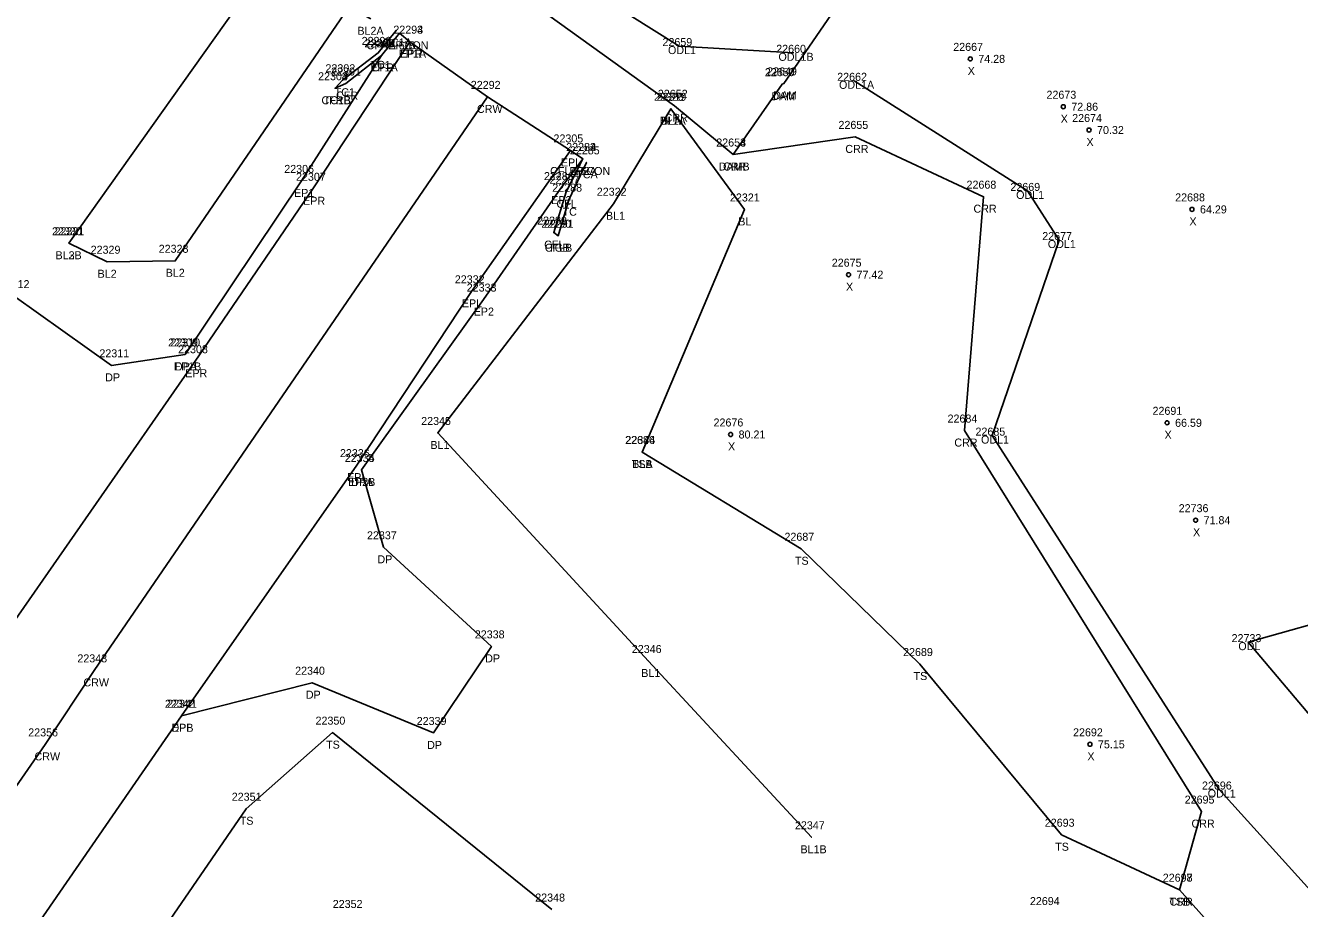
# Model space of a CAD drawing. Extents: x 2266664 to 2272385, y 716533 to 724777.
# Drawn here: x 2271014.2 to 2271173.4, y 722788.6 to 722898.9 of the extents above; entities that cross this region are included whole.
import ezdxf

# ---------------------------------------------------------------- set-up
doc = ezdxf.new("R2010")
doc.units = 0
for name, color, linetype in [('RD_DTM_BkLn1', 7, 'Continuous'), ('RD_DTM_BkLn2', 7, 'Continuous'), ('RD_EX_Conc', 7, 'Continuous'), ('RD_EX_Conc_txCode', 7, 'Continuous'), ('RD_EX_Dam', 7, 'Continuous'), ('RD_EX_Dam_txCode', 7, 'Continuous'), ('RD_EX_Driveway', 7, 'Continuous'), ('RD_EX_Driveway_txCode', 7, 'Continuous'), ('RD_EX_H2O', 7, 'Continuous'), ('RD_EX_H2O_txCode', 7, 'Continuous'), ('RD_EX_Road', 7, 'Continuous'), ('RD_EX_Road_txCode', 7, 'Continuous'), ('RD_Sketch8', 7, 'Continuous'), ('RD_SMD_Locator', 7, 'Continuous'), ('RD_SMD_Misc', 7, 'Continuous')]:
    doc.layers.add(name, color=color, linetype=linetype)

msp = doc.modelspace()

# ---------------------------------------------------------------- linework, layer by layer
at = {"layer": 'RD_DTM_BkLn1'}
for points in [[(2271062.16, 722908.42), (2271054.75, 722912.5), (2271044.28, 722906.51), (2271019.61, 722871.71)], [(2271057.34, 722899.76), (2271054.56, 722901.22), (2271032.9, 722869.52), (2271024.4, 722869.4), (2271019.61, 722871.71)], [(2271071.9, 722890), (2271022.74, 722818.33), (2271016.63, 722809.08), (2270958.33, 722725.01), (2270901.32, 722642.18), (2270840.59, 722553.52), (2270785.24, 722472.83), (2270728.9, 722390.97), (2270676.09, 722314.01), (2270618.86, 722231.46), (2270562.47, 722149.97), (2270509.04, 722072.31)], [(2271094.83, 722888.51), (2271087.64, 722876.65), (2271065.7, 722848), (2271092.04, 722819.5), (2271112.4, 722797.47)], [(2271094.83, 722888.51), (2271104, 722875.93), (2271091.22, 722845.62)]]:
    msp.add_lwpolyline(points, dxfattribs=at)
at = {"layer": 'RD_DTM_BkLn2'}
for points in [[(2271060.48, 722898.3), (2271058.25, 722895.5), (2271053.77, 722892.08), (2271052.86, 722891.08)], [(2271084.28, 722881.82), (2271082.08, 722877.15), (2271080.75, 722872.65)], [(2271091.22, 722845.62), (2271111.11, 722833.53), (2271125.94, 722819.12), (2271143.64, 722797.79), (2271158.38, 722790.92)], [(2271079.95, 722788.44), (2271052.54, 722810.55), (2271041.74, 722801.04), (2270977.44, 722707.42), (2270923.09, 722625.66), (2270862.03, 722536.61), (2270804.48, 722457.1), (2270748.57, 722375.78), (2270696.23, 722299.13), (2270638.45, 722212.76), (2270584.52, 722135.08), (2270530.44, 722055.94)]]:
    msp.add_lwpolyline(points, dxfattribs=at)
at = {"layer": 'RD_EX_Conc'}
for points in [[(2271060.91, 722897.95), (2271058.68, 722895.19), (2271054.21, 722891.67), (2271052.86, 722891.08)], [(2271083.82, 722882.24), (2271081.73, 722878.14), (2271080.19, 722873.04), (2271080.75, 722872.65)]]:
    msp.add_lwpolyline(points, dxfattribs=at)
at = {"layer": 'RD_EX_Dam'}
msp.add_lwpolyline([(2271152.21, 722956.41), (2271134.6, 722929.34), (2271126.04, 722916.39), (2271125.72, 722916.12), (2271108.94, 722891.69), (2271108.71, 722891.59), (2271102.6, 722882.8)], dxfattribs=at)
at = {"layer": 'RD_EX_Driveway'}
for points in [[(2271034.11, 722857.81), (2271024.92, 722856.45), (2271012.76, 722865.1), (2271006.76, 722871.86), (2270994.96, 722862.93), (2271003.93, 722846.02), (2271009.12, 722830.75), (2271009.25, 722819.48)], [(2271056.15, 722843.38), (2271058.93, 722833.71), (2271072.4, 722821.33), (2271065.14, 722810.51), (2271049.99, 722816.79), (2271033.67, 722812.66)]]:
    msp.add_lwpolyline(points, dxfattribs=at)
at = {"layer": 'RD_EX_H2O'}
for points in [[(2271066.1, 722930.8), (2271065.74, 722921.6), (2271073.98, 722910.09), (2271095.87, 722896.35), (2271110.14, 722895.51)], [(2271064.14, 722911.29), (2271095.29, 722888.89), (2271102.6, 722882.8), (2271117.86, 722885), (2271133.88, 722877.53), (2271131.49, 722848.3), (2271161.12, 722800.68), (2271158.38, 722790.92), (2271209.97, 722733.05), (2271257.97, 722699.07), (2271328.71, 722663.53), (2271328.76, 722676.23), (2271359.03, 722679.94), (2271405.02, 722657.62), (2271442.98, 722642.77), (2271440.33, 722616.88), (2271427.19, 722613.92), (2271489.22, 722575.87)], [(2271129.36, 722911.84), (2271153.18, 722901.48), (2271155.78, 722900.51), (2271177.85, 722902.74), (2271201.84, 722887.34), (2271215.1, 722884.79), (2271219.95, 722858.82), (2271232.72, 722821.83), (2271249.45, 722774.17), (2271246.55, 722773.42), (2271242.67, 722777.55), (2271238.21, 722784.89), (2271226, 722791.87), (2271212.02, 722807.07), (2271179.99, 722825.53), (2271166.96, 722821.86), (2271183.23, 722802.58), (2271216.87, 722768.55), (2271264.5, 722731.34), (2271320.51, 722707.37), (2271341.1, 722714.58), (2271416.82, 722677.3), (2271508.46, 722629.61)], [(2271117.72, 722892.01), (2271139.37, 722878.25), (2271143.33, 722872.11), (2271134.98, 722847.67), (2271163.31, 722803.44), (2271218.79, 722742.09), (2271259.36, 722713.19), (2271326.22, 722679.37), (2271360.14, 722683.15), (2271408.13, 722662.76), (2271445.34, 722648.77), (2271452.06, 722619.67), (2271495.73, 722594.36)]]:
    msp.add_lwpolyline(points, dxfattribs=at)
at = {"layer": 'RD_EX_Road'}
for p, q in [((2271062.22, 722896.9), (2271060.91, 722897.95)), ((2271082.27, 722883.31), (2271083.82, 722882.24))]:
    msp.add_line(p, q, dxfattribs=at)
for points in [[(2271062.22, 722896.9), (2271050.1, 722878.52), (2271035.36, 722856.97), (2271009.25, 722819.48), (2270948.68, 722732.14), (2270891.73, 722649.3), (2270830.29, 722559.72), (2270774.71, 722479.03), (2270718.54, 722397.26), (2270665.83, 722320.36), (2270608.79, 722237.92), (2270552.34, 722156.58), (2270498.7, 722078.55)], [(2271082.27, 722883.31), (2271071.9, 722890), (2271062.22, 722896.9)], [(2271058.68, 722895.19), (2271048.65, 722879.5), (2271034.11, 722857.81)], [(2271082.27, 722883.31), (2271069.9, 722865.7), (2271055.57, 722843.98), (2271033.67, 722812.66), (2270967.43, 722716.72), (2270911.49, 722634.76), (2270850.44, 722546.34), (2270794.45, 722465.06), (2270738.33, 722383.22), (2270685.67, 722306.46), (2270626.75, 722221.55), (2270572.84, 722143.55), (2270518.64, 722064.54)], [(2271083.82, 722882.24), (2271081.07, 722878.6), (2271071.39, 722864.67), (2271056.15, 722843.38)]]:
    msp.add_lwpolyline(points, dxfattribs=at)
at = {"layer": 'RD_SMD_Locator'}
for centre, radius in [((2271060.48, 722898.3), 0.001), ((2271060.91, 722897.95), 0.001), ((2271060.91, 722897.95), 0.001), ((2271062.22, 722896.9), 0.001), ((2271062.22, 722896.9), 0.001), ((2271058.25, 722895.5), 0.001), ((2271058.68, 722895.19), 0.001), ((2271058.68, 722895.19), 0.001), ((2271095.87, 722896.35), 0.001), ((2271110.14, 722895.51), 0.001), ((2271132.23, 722894.75), 0.25), ((2271053.77, 722892.08), 0.001), ((2271054.21, 722891.67), 0.001), ((2271108.94, 722891.69), 0.001), ((2271117.72, 722892.01), 0.001), ((2271052.86, 722891.08), 0.001), ((2271052.86, 722891.08), 0.001), ((2271108.71, 722891.59), 0.001), ((2271071.9, 722890), 0.001), ((2271094.83, 722888.51), 0.001), ((2271094.83, 722888.51), 0.001), ((2271095.29, 722888.89), 0.001), ((2271143.85, 722888.77), 0.25), ((2271147.07, 722885.86), 0.25), ((2271117.86, 722885), 0.001), ((2271082.27, 722883.31), 0.001), ((2271083.82, 722882.24), 0.001), ((2271083.82, 722882.24), 0.001), ((2271102.6, 722882.8), 0.001), ((2271102.6, 722882.8), 0.001), ((2271084.28, 722881.82), 0.001), ((2271048.65, 722879.5), 0.001), ((2271050.1, 722878.52), 0.001), ((2271081.07, 722878.6), 0.001), ((2271081.73, 722878.14), 0.001), ((2271133.88, 722877.53), 0.001), ((2271139.37, 722878.25), 0.001), ((2271082.08, 722877.15), 0.001), ((2271087.64, 722876.65), 0.001), ((2271104, 722875.93), 0.001), ((2271159.93, 722875.94), 0.25), ((2271080.19, 722873.04), 0.001), ((2271080.75, 722872.65), 0.001), ((2271080.75, 722872.65), 0.001), ((2271019.61, 722871.71), 0.001), ((2271019.61, 722871.71), 0.001), ((2271143.33, 722872.11), 0.001), ((2271024.4, 722869.4), 0.001), ((2271032.9, 722869.52), 0.001), ((2271117.02, 722867.78), 0.25), ((2271069.9, 722865.7), 0.001), ((2271071.39, 722864.67), 0.001), ((2271034.11, 722857.81), 0.001), ((2271034.11, 722857.81), 0.001), ((2271035.36, 722856.97), 0.001), ((2271024.92, 722856.45), 0.001), ((2271156.82, 722849.27), 0.25), ((2271065.7, 722848), 0.001), ((2271102.28, 722847.81), 0.25), ((2271131.49, 722848.3), 0.001), ((2271134.98, 722847.67), 0.001), ((2271091.22, 722845.62), 0.001), ((2271091.22, 722845.62), 0.001), ((2271055.57, 722843.98), 0.001), ((2271056.15, 722843.38), 0.001), ((2271056.15, 722843.38), 0.001), ((2271160.38, 722837.1), 0.25), ((2271058.93, 722833.71), 0.001), ((2271111.11, 722833.53), 0.001), ((2271166.96, 722821.86), 0.001), ((2271072.4, 722821.33), 0.001), ((2271092.04, 722819.5), 0.001), ((2271125.94, 722819.12), 0.001), ((2271022.74, 722818.33), 0.001), ((2271049.99, 722816.79), 0.001), ((2271033.67, 722812.66), 0.001), ((2271033.67, 722812.66), 0.001), ((2271052.54, 722810.55), 0.001), ((2271065.14, 722810.51), 0.001), ((2271016.63, 722809.08), 0.001), ((2271147.18, 722809.09), 0.25), ((2271163.31, 722803.44), 0.001), ((2271041.74, 722801.04), 0.001), ((2271161.12, 722800.68), 0.001), ((2271143.64, 722797.79), 0.001), ((2271112.4, 722797.47), 0.001), ((2271158.38, 722790.92), 0.001), ((2271158.38, 722790.92), 0.001)]:
    msp.add_circle(centre, radius, dxfattribs=at)

# ---------------------------------------------------------------- texts
at = {"layer": 'RD_EX_Conc_txCode'}
for s, p in [('22299', (2271056.6, 722896.19)), ('CFRA 6CON', (2271056.8, 722895.95)), ('22301', (2271052.37, 722892.67)), ('CFR', (2271057.45, 722893.19)), ('22304', (2271050.74, 722892.08)), ('CFRB', (2271051.16, 722889.08)), ('CFR', (2271052.98, 722889.67)), ('22284', (2271081.74, 722883.24)), ('CFLA 6CON', (2271079.73, 722880.24)), ('22287', (2271079.65, 722879.14)), ('CFL', (2271080.53, 722876.14)), ('22289', (2271078.11, 722874.04)), ('22290', (2271078.63, 722873.65)), ('CFL', (2271078.99, 722871.04)), ('CFLB', (2271079.07, 722870.65))]:
    msp.add_text(s, height=1, dxfattribs=at).set_placement(p)
at = {"layer": 'RD_EX_Dam_txCode'}
for s, p in [('22650', (2271106.56, 722892.59)), ('22649', (2271106.84, 722892.69)), ('DAM', (2271107.38, 722889.59)), ('DAM', (2271107.61, 722889.69)), ('22653', (2271100.49, 722883.8)), ('DAMB', (2271100.79, 722880.8))]:
    msp.add_text(s, height=1, dxfattribs=at).set_placement(p)
at = {"layer": 'RD_EX_Driveway_txCode'}
for s, p in [('22312', (2271010.96, 722866.1)), ('22310', (2271032.28, 722858.81)), ('22311', (2271023.41, 722857.45)), ('DPA', (2271032.85, 722855.81)), ('DP', (2271024.14, 722854.45)), ('22335', (2271054.07, 722844.38)), ('DPA', (2271054.88, 722841.38)), ('22337', (2271056.85, 722834.71)), ('DP', (2271058.15, 722831.71)), ('22338', (2271070.32, 722822.33)), ('DP', (2271071.62, 722819.33)), ('22340', (2271047.87, 722817.79)), ('DP', (2271049.21, 722814.79)), ('22341', (2271031.88, 722813.66)), ('22339', (2271063.06, 722811.51)), ('DPB', (2271032.42, 722810.66)), ('DP', (2271064.36, 722808.51))]:
    msp.add_text(s, height=1, dxfattribs=at).set_placement(p)
at = {"layer": 'RD_EX_H2O_txCode'}
for s, p in [('22659', (2271093.77, 722896.35)), ('22660', (2271107.98, 722895.51)), ('ODL1', (2271094.46, 722895.35)), ('ODL1B', (2271108.26, 722894.51)), ('22662', (2271115.6, 722892.01)), ('ODL1A', (2271115.83, 722891.01)), ('22652', (2271093.19, 722889.89)), ('CRR', (2271094.04, 722886.89)), ('22655', (2271115.76, 722886)), ('22654', (2271100.49, 722883.8)), ('CRR', (2271116.61, 722883)), ('CRR', (2271101.34, 722880.8)), ('22668', (2271131.76, 722878.53)), ('22669', (2271137.24, 722878.25)), ('ODL1', (2271137.96, 722877.25)), ('CRR', (2271132.63, 722875.53)), ('22677', (2271141.22, 722872.11)), ('ODL1', (2271141.92, 722871.11)), ('22684', (2271129.39, 722849.3)), ('22685', (2271132.88, 722847.67)), ('CRR', (2271130.24, 722846.3)), ('ODL1', (2271133.57, 722846.67)), ('22733', (2271164.88, 722821.86)), ('ODL', (2271165.72, 722820.86)), ('22696', (2271161.18, 722803.44)), ('22695', (2271159.02, 722801.68)), ('ODL1', (2271161.9, 722802.44)), ('CRR', (2271159.87, 722798.68)), ('22698', (2271156.28, 722791.92)), ('CRR', (2271157.13, 722788.92))]:
    msp.add_text(s, height=1, dxfattribs=at).set_placement(p)
at = {"layer": 'RD_EX_Road_txCode'}
for s, p in [('22293', (2271060.14, 722897.9)), ('22294', (2271060.14, 722897.9)), ('22300', (2271056.52, 722896.19)), ('EP1B', (2271059.52, 722895.95)), ('EP1A', (2271060.81, 722894.9)), ('EPR', (2271060.99, 722894.9)), ('EP1A', (2271057.27, 722893.19)), ('22305', (2271080.15, 722884.31)), ('22283', (2271081.74, 722883.24)), ('EPL', (2271081.07, 722881.31)), ('22306', (2271046.51, 722880.5)), ('22307', (2271047.98, 722879.52)), ('22286', (2271078.96, 722879.6)), ('EP2A', (2271082.13, 722880.24)), ('EP1', (2271047.73, 722877.5)), ('EPR', (2271048.87, 722876.52)), ('EP2', (2271079.86, 722876.6)), ('22332', (2271067.82, 722866.7)), ('22333', (2271069.31, 722865.67)), ('EPL', (2271068.7, 722863.7)), ('EP2', (2271070.18, 722862.67)), ('22309', (2271032, 722858.81)), ('22308', (2271033.25, 722857.97)), ('EP1B', (2271032.72, 722855.81)), ('EPR', (2271034.14, 722854.97)), ('22336', (2271053.47, 722844.98)), ('22334', (2271054.07, 722844.38)), ('EPL', (2271054.36, 722841.98)), ('EP2B', (2271054.47, 722841.38)), ('22342', (2271031.6, 722813.66)), ('EPL', (2271032.47, 722810.66))]:
    msp.add_text(s, height=1, dxfattribs=at).set_placement(p)
at = {"layer": 'RD_Sketch8'}
for s, p in [('22667', (2271130.1, 722895.75)), ('74.28', (2271133.23, 722894.25)), ('X', (2271131.91, 722892.75)), ('22673', (2271141.75, 722889.77)), ('72.86', (2271144.85, 722888.27)), ('X', (2271143.53, 722886.77)), ('22674', (2271144.96, 722886.86)), ('70.32', (2271148.07, 722885.36)), ('X', (2271146.75, 722883.86)), ('22688', (2271157.83, 722876.94)), ('64.29', (2271160.93, 722875.44)), ('X', (2271159.61, 722873.94)), ('22675', (2271114.92, 722868.78)), ('77.42', (2271118.02, 722867.28)), ('X', (2271116.7, 722865.78)), ('22691', (2271155, 722850.27)), ('22676', (2271100.15, 722848.81)), ('66.59', (2271157.82, 722848.77)), ('80.21', (2271103.28, 722847.31)), ('X', (2271156.5, 722847.27)), ('X', (2271101.96, 722845.81)), ('22736', (2271158.27, 722838.1)), ('71.84', (2271161.38, 722836.6)), ('X', (2271160.06, 722835.1)), ('22692', (2271145.07, 722810.09)), ('75.15', (2271148.18, 722808.59)), ('X', (2271146.86, 722807.09)), ('22694', (2271139.68, 722789))]:
    msp.add_text(s, height=1, dxfattribs=at).set_placement(p)
at = {"layer": 'RD_SMD_Misc'}
for s, p in [('BL2A', (2271055.65, 722897.76)), ('22298', (2271056.18, 722896.5)), ('TC1A', (2271059.03, 722896.3)), ('22302', (2271051.66, 722893.08)), ('TC1', (2271057.29, 722893.5)), ('22303', (2271050.74, 722892.08)), ('22292', (2271069.82, 722891)), ('TC1B', (2271051.43, 722889.08)), ('TC1', (2271052.81, 722890.08)), ('22320', (2271092.71, 722889.51)), ('22319', (2271093.03, 722889.51)), ('CRW', (2271070.59, 722888)), ('BL1A', (2271093.42, 722886.51)), ('BLA', (2271093.58, 722886.51)), ('22285', (2271082.2, 722882.82)), ('TCA', (2271083, 722879.82)), ('22288', (2271080, 722878.15)), ('22322', (2271085.56, 722877.65)), ('22321', (2271102.2, 722876.93)), ('TC', (2271081.29, 722875.15)), ('22291', (2271078.95, 722873.65)), ('BL1', (2271086.71, 722874.65)), ('BL', (2271103.24, 722873.93)), ('22330', (2271017.49, 722872.71)), ('22331', (2271017.81, 722872.71)), ('22329', (2271022.32, 722870.4)), ('22328', (2271030.82, 722870.52)), ('TCB', (2271079.48, 722870.65)), ('BL2B', (2271017.93, 722869.71)), ('BL3B', (2271017.93, 722869.71)), ('BL2', (2271023.19, 722867.4)), ('BL2', (2271031.7, 722867.52)), ('22345', (2271063.62, 722849)), ('22686', (2271089.1, 722846.62)), ('22344', (2271089.14, 722846.62)), ('BL1', (2271064.77, 722846)), ('TSA', (2271089.94, 722843.62)), ('BLB', (2271089.99, 722843.62)), ('22687', (2271109.01, 722834.53)), ('TS', (2271110.32, 722831.53)), ('22343', (2271020.66, 722819.33)), ('22346', (2271089.94, 722820.5)), ('22689', (2271123.83, 722820.12)), ('BL1', (2271091.12, 722817.5)), ('CRW', (2271021.42, 722816.33)), ('TS', (2271125.14, 722817.12)), ('22350', (2271050.42, 722811.55)), ('22356', (2271014.52, 722810.08)), ('TS', (2271051.74, 722808.55)), ('CRW', (2271015.31, 722807.08)), ('22351', (2271039.95, 722802.04)), ('TS', (2271040.95, 722799.04)), ('22347', (2271110.32, 722798.47)), ('22693', (2271141.54, 722798.79)), ('BL1B', (2271111.01, 722795.47)), ('TS', (2271142.84, 722795.79)), ('22697', (2271156.28, 722791.92)), ('22348', (2271077.87, 722789.44)), ('TSB', (2271157.11, 722788.92)), ('22352', (2271052.57, 722788.64))]:
    msp.add_text(s, height=1, dxfattribs=at).set_placement(p)

doc.saveas('drawing.dxf')
